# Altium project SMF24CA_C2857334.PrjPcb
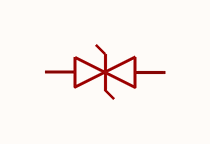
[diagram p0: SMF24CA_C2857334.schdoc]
1 sheet, 1 parts. Net scope: global (net labels, ports and power ports of the same name join across sheets).

## Sheet SMF24CA_C2857334.schdoc
size 127 x 101 mm

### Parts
D?  smf24ca_c2857334  [SOD-123FL_L2.8-W1.8-LS3.7-BI]  (value not drawn)

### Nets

Not connected (* = marked no-connect by the designer): D? 1 2

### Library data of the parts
D? = smf24ca_c2857334: 极性:双向;反向截止电压(Vrwm):24V;钳位电压:38.9V;峰值脉冲电流(Ipp):5.1A;峰值脉冲功率(Ppp):200W@10/1000us;击穿电压(VBR):26.7V;; Manufacturer: JSMSEMI(杰盛微); AddInBom: yes; ModelId: d105299b3871451c86f679efef28ff8f; ModelTransform: 145.669,70.866,0,0,0,0,0,0,0; Polarity: 双向; Reverse Stand-Off Voltage (Vrwm): 24V; Clamping Voltage: 38.9V; Peak Pulse Current (Ipp): 5.1A; Voltage - Breakdown: 26.7V; Reverse Leakage Current (Ir): 1uA; Number of Channels: 单路; Type: TVS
